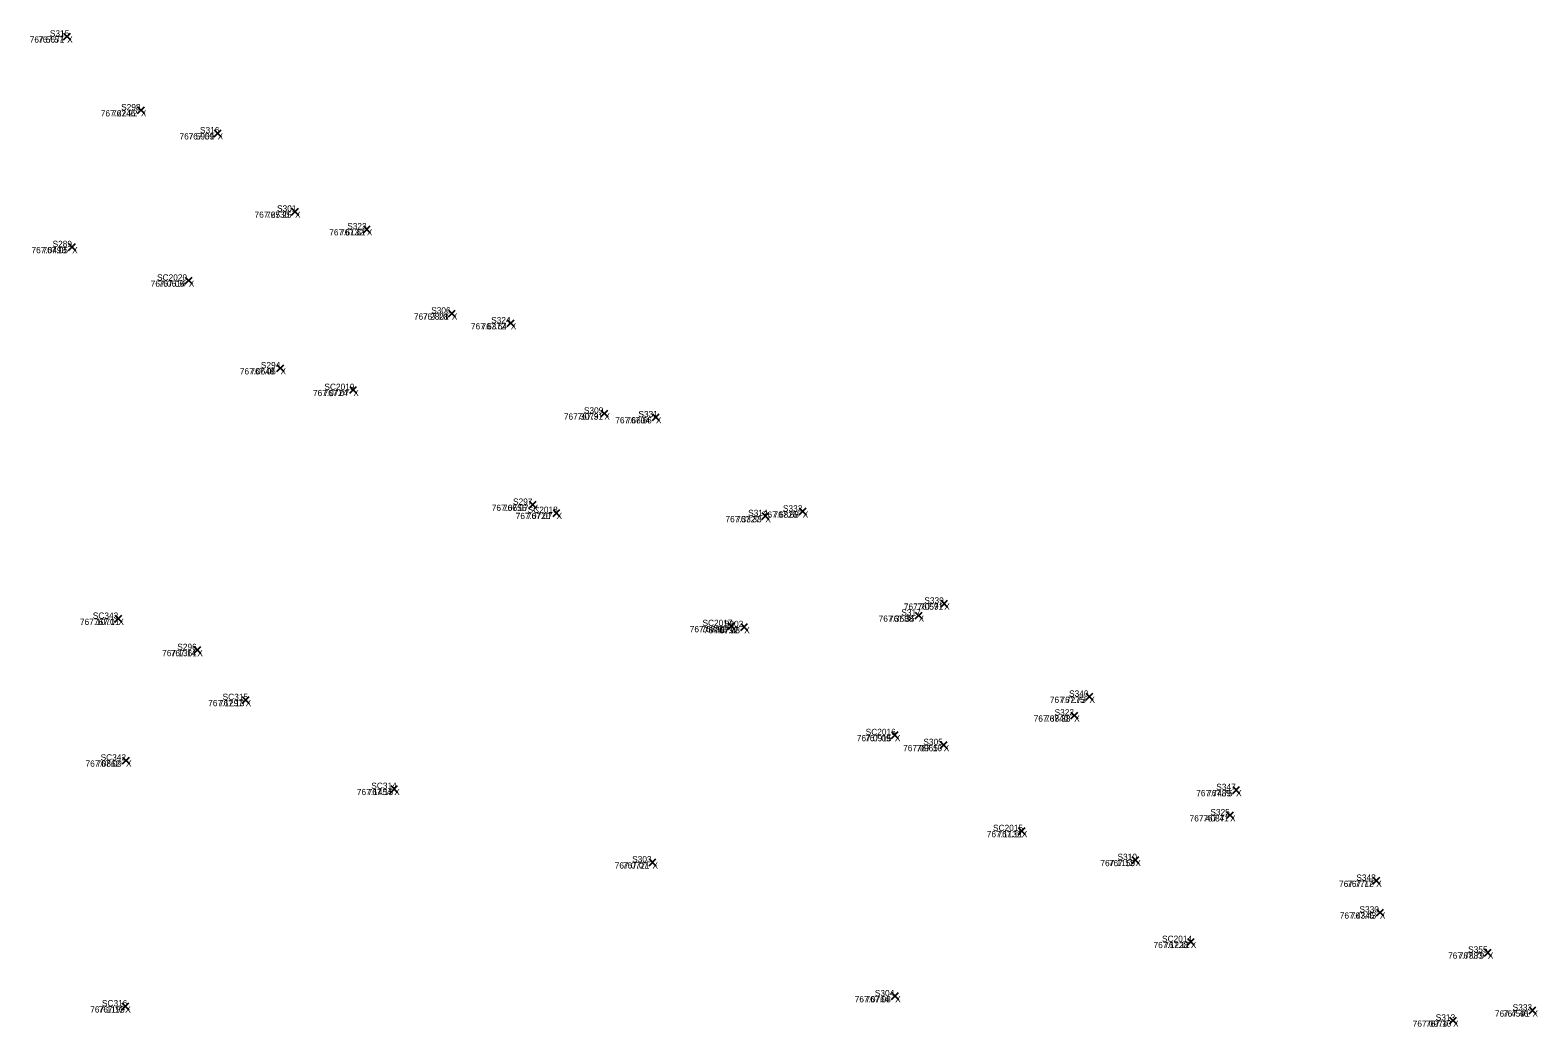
# Model space of a CAD drawing. Extents: x 1845019 to 1877956, y 680444 to 701081.
# Drawn here: x 1857662.66 to 1857677.19, y 694290.37 to 694299.98 of the extents above; entities that cross this region are included whole.
import ezdxf

# ---------------------------------------------------------------- set-up
doc = ezdxf.new("R2010")
doc.units = 0
for name, color, linetype in [('SV_X_Random_Point', 7, 'Continuous'), ('SV_X_Text_Comment', 7, 'Continuous'), ('SV_X_Text_Elevation', 7, 'Continuous'), ('SV_X_Text_Name', 7, 'Continuous')]:
    doc.layers.add(name, color=color, linetype=linetype)

msp = doc.modelspace()

# ---------------------------------------------------------------- linework, layer by layer
at = {"layer": 'SV_X_Random_Point'}
for p, q in [((1857662.984, 694299.886), (1857663.051, 694299.952)), ((1857662.984, 694299.952), (1857663.051, 694299.886)), ((1857662.984, 694299.886), (1857663.051, 694299.952)), ((1857662.984, 694299.952), (1857663.051, 694299.886)), ((1857663.695, 694299.175), (1857663.762, 694299.241)), ((1857663.695, 694299.241), (1857663.762, 694299.175)), ((1857663.695, 694299.175), (1857663.762, 694299.241)), ((1857663.695, 694299.241), (1857663.762, 694299.175)), ((1857664.435, 694298.953), (1857664.502, 694299.019)), ((1857664.435, 694299.019), (1857664.502, 694298.953)), ((1857664.435, 694298.953), (1857664.502, 694299.019)), ((1857664.435, 694299.019), (1857664.502, 694298.953)), ((1857665.18, 694298.197), (1857665.247, 694298.264)), ((1857665.18, 694298.264), (1857665.247, 694298.197)), ((1857665.18, 694298.197), (1857665.247, 694298.264)), ((1857665.18, 694298.264), (1857665.247, 694298.197)), ((1857665.873, 694298.027), (1857665.939, 694298.094)), ((1857665.873, 694298.094), (1857665.939, 694298.027)), ((1857665.873, 694298.027), (1857665.939, 694298.094)), ((1857665.873, 694298.094), (1857665.939, 694298.027)), ((1857663.032, 694297.856), (1857663.099, 694297.923)), ((1857663.032, 694297.923), (1857663.099, 694297.856)), ((1857663.032, 694297.856), (1857663.099, 694297.923)), ((1857663.032, 694297.923), (1857663.099, 694297.856)), ((1857664.156, 694297.533), (1857664.223, 694297.6)), ((1857664.156, 694297.6), (1857664.223, 694297.533)), ((1857664.156, 694297.533), (1857664.223, 694297.6)), ((1857664.156, 694297.6), (1857664.223, 694297.533)), ((1857666.692, 694297.215), (1857666.759, 694297.282)), ((1857666.692, 694297.282), (1857666.759, 694297.215)), ((1857666.692, 694297.215), (1857666.759, 694297.282)), ((1857666.692, 694297.282), (1857666.759, 694297.215)), ((1857667.26, 694297.122), (1857667.326, 694297.188)), ((1857667.26, 694297.188), (1857667.326, 694297.122)), ((1857667.26, 694297.122), (1857667.326, 694297.188)), ((1857667.26, 694297.188), (1857667.326, 694297.122)), ((1857665.04, 694296.688), (1857665.107, 694296.754)), ((1857665.04, 694296.754), (1857665.107, 694296.688)), ((1857665.04, 694296.688), (1857665.107, 694296.754)), ((1857665.04, 694296.754), (1857665.107, 694296.688)), ((1857665.741, 694296.479), (1857665.808, 694296.545)), ((1857665.741, 694296.545), (1857665.808, 694296.479)), ((1857665.741, 694296.479), (1857665.808, 694296.545)), ((1857665.741, 694296.545), (1857665.808, 694296.479)), ((1857668.162, 694296.252), (1857668.228, 694296.318)), ((1857668.162, 694296.318), (1857668.228, 694296.252)), ((1857668.162, 694296.252), (1857668.228, 694296.318)), ((1857668.162, 694296.318), (1857668.228, 694296.252)), ((1857668.659, 694296.216), (1857668.725, 694296.282)), ((1857668.659, 694296.282), (1857668.725, 694296.216)), ((1857668.659, 694296.216), (1857668.725, 694296.282)), ((1857668.659, 694296.282), (1857668.725, 694296.216)), ((1857667.471, 694295.372), (1857667.537, 694295.439)), ((1857667.471, 694295.439), (1857667.537, 694295.372)), ((1857667.471, 694295.372), (1857667.537, 694295.439)), ((1857667.471, 694295.439), (1857667.537, 694295.372)), ((1857667.701, 694295.293), (1857667.767, 694295.36)), ((1857667.701, 694295.36), (1857667.767, 694295.293)), ((1857667.701, 694295.293), (1857667.767, 694295.36)), ((1857667.701, 694295.36), (1857667.767, 694295.293)), ((1857670.074, 694295.307), (1857670.14, 694295.374)), ((1857670.074, 694295.374), (1857670.14, 694295.307)), ((1857670.074, 694295.307), (1857670.14, 694295.374)), ((1857670.074, 694295.374), (1857670.14, 694295.307)), ((1857669.714, 694295.263), (1857669.781, 694295.329)), ((1857669.714, 694295.329), (1857669.781, 694295.263)), ((1857669.714, 694295.263), (1857669.781, 694295.329)), ((1857669.714, 694295.329), (1857669.781, 694295.263)), ((1857671.437, 694294.419), (1857671.504, 694294.486)), ((1857671.437, 694294.486), (1857671.504, 694294.419)), ((1857671.437, 694294.419), (1857671.504, 694294.486)), ((1857671.437, 694294.486), (1857671.504, 694294.419)), ((1857663.478, 694294.273), (1857663.544, 694294.34)), ((1857663.478, 694294.34), (1857663.544, 694294.273)), ((1857663.478, 694294.273), (1857663.544, 694294.34)), ((1857663.478, 694294.34), (1857663.544, 694294.273)), ((1857671.191, 694294.304), (1857671.257, 694294.371)), ((1857671.191, 694294.371), (1857671.257, 694294.304)), ((1857671.191, 694294.304), (1857671.257, 694294.371)), ((1857671.191, 694294.371), (1857671.257, 694294.304)), ((1857669.385, 694294.203), (1857669.452, 694294.27)), ((1857669.385, 694294.27), (1857669.452, 694294.203)), ((1857669.385, 694294.203), (1857669.452, 694294.27)), ((1857669.385, 694294.27), (1857669.452, 694294.203)), ((1857669.51, 694294.193), (1857669.576, 694294.26)), ((1857669.51, 694294.26), (1857669.576, 694294.193)), ((1857669.51, 694294.193), (1857669.576, 694294.26)), ((1857669.51, 694294.26), (1857669.576, 694294.193)), ((1857664.239, 694293.971), (1857664.305, 694294.038)), ((1857664.239, 694294.038), (1857664.305, 694293.971)), ((1857664.239, 694293.971), (1857664.305, 694294.038)), ((1857664.239, 694294.038), (1857664.305, 694293.971)), ((1857672.837, 694293.522), (1857672.904, 694293.588)), ((1857672.837, 694293.588), (1857672.904, 694293.522)), ((1857672.837, 694293.522), (1857672.904, 694293.588)), ((1857672.837, 694293.588), (1857672.904, 694293.522)), ((1857664.705, 694293.49), (1857664.771, 694293.556)), ((1857664.705, 694293.556), (1857664.771, 694293.49)), ((1857664.705, 694293.49), (1857664.771, 694293.556)), ((1857664.705, 694293.556), (1857664.771, 694293.49)), ((1857672.69, 694293.34), (1857672.757, 694293.407)), ((1857672.69, 694293.407), (1857672.757, 694293.34)), ((1857672.69, 694293.34), (1857672.757, 694293.407)), ((1857672.69, 694293.407), (1857672.757, 694293.34)), ((1857670.962, 694293.151), (1857671.028, 694293.218)), ((1857670.962, 694293.218), (1857671.028, 694293.151)), ((1857670.962, 694293.151), (1857671.028, 694293.218)), ((1857670.962, 694293.218), (1857671.028, 694293.151)), ((1857671.433, 694293.056), (1857671.5, 694293.122)), ((1857671.433, 694293.122), (1857671.5, 694293.056)), ((1857671.433, 694293.056), (1857671.5, 694293.122)), ((1857671.433, 694293.122), (1857671.5, 694293.056)), ((1857663.552, 694292.906), (1857663.619, 694292.973)), ((1857663.552, 694292.973), (1857663.619, 694292.906)), ((1857663.552, 694292.906), (1857663.619, 694292.973)), ((1857663.552, 694292.973), (1857663.619, 694292.906)), ((1857666.137, 694292.632), (1857666.203, 694292.699)), ((1857666.137, 694292.699), (1857666.203, 694292.632)), ((1857666.137, 694292.632), (1857666.203, 694292.699)), ((1857666.137, 694292.699), (1857666.203, 694292.632)), ((1857674.251, 694292.622), (1857674.317, 694292.689)), ((1857674.251, 694292.689), (1857674.317, 694292.622)), ((1857674.251, 694292.622), (1857674.317, 694292.689)), ((1857674.251, 694292.689), (1857674.317, 694292.622)), ((1857674.193, 694292.379), (1857674.259, 694292.445)), ((1857674.193, 694292.445), (1857674.259, 694292.379)), ((1857674.193, 694292.379), (1857674.259, 694292.445)), ((1857674.193, 694292.445), (1857674.259, 694292.379)), ((1857672.185, 694292.227), (1857672.251, 694292.294)), ((1857672.185, 694292.294), (1857672.251, 694292.227)), ((1857672.185, 694292.227), (1857672.251, 694292.294)), ((1857672.185, 694292.294), (1857672.251, 694292.227)), ((1857668.626, 694291.925), (1857668.693, 694291.992)), ((1857668.626, 694291.992), (1857668.693, 694291.925)), ((1857668.626, 694291.925), (1857668.693, 694291.992)), ((1857668.626, 694291.992), (1857668.693, 694291.925)), ((1857673.28, 694291.948), (1857673.347, 694292.014)), ((1857673.28, 694292.014), (1857673.347, 694291.948)), ((1857673.28, 694291.948), (1857673.347, 694292.014)), ((1857673.28, 694292.014), (1857673.347, 694291.948)), ((1857675.601, 694291.747), (1857675.668, 694291.814)), ((1857675.601, 694291.814), (1857675.668, 694291.747)), ((1857675.601, 694291.747), (1857675.668, 694291.814)), ((1857675.601, 694291.814), (1857675.668, 694291.747)), ((1857675.636, 694291.441), (1857675.703, 694291.508)), ((1857675.636, 694291.508), (1857675.703, 694291.441)), ((1857675.636, 694291.441), (1857675.703, 694291.508)), ((1857675.636, 694291.508), (1857675.703, 694291.441)), ((1857673.814, 694291.158), (1857673.88, 694291.225)), ((1857673.814, 694291.225), (1857673.88, 694291.158)), ((1857673.814, 694291.158), (1857673.88, 694291.225)), ((1857673.814, 694291.225), (1857673.88, 694291.158)), ((1857676.677, 694291.055), (1857676.743, 694291.122)), ((1857676.677, 694291.122), (1857676.743, 694291.055)), ((1857676.677, 694291.055), (1857676.743, 694291.122)), ((1857676.677, 694291.122), (1857676.743, 694291.055)), ((1857670.964, 694290.635), (1857671.031, 694290.702)), ((1857670.964, 694290.702), (1857671.031, 694290.635)), ((1857670.964, 694290.635), (1857671.031, 694290.702)), ((1857670.964, 694290.702), (1857671.031, 694290.635)), ((1857663.545, 694290.536), (1857663.612, 694290.603)), ((1857663.545, 694290.603), (1857663.612, 694290.536)), ((1857663.545, 694290.536), (1857663.612, 694290.603)), ((1857663.545, 694290.603), (1857663.612, 694290.536)), ((1857677.107, 694290.497), (1857677.174, 694290.564)), ((1857677.107, 694290.564), (1857677.174, 694290.497)), ((1857677.107, 694290.497), (1857677.174, 694290.564)), ((1857677.107, 694290.564), (1857677.174, 694290.497)), ((1857676.342, 694290.4), (1857676.409, 694290.466)), ((1857676.342, 694290.466), (1857676.409, 694290.4)), ((1857676.342, 694290.4), (1857676.409, 694290.466)), ((1857676.342, 694290.466), (1857676.409, 694290.4))]:
    msp.add_line(p, q, dxfattribs=at)

# ---------------------------------------------------------------- texts
at = {"layer": 'SV_X_Text_Comment'}
for p in [(1857663.018, 694299.859), (1857663.728, 694299.148), (1857664.468, 694298.926), (1857665.214, 694298.171), (1857665.906, 694298.001), (1857663.066, 694297.829), (1857664.19, 694297.506), (1857666.725, 694297.189), (1857667.293, 694297.095), (1857665.074, 694296.661), (1857665.775, 694296.452), (1857668.195, 694296.225), (1857668.692, 694296.189), (1857667.504, 694295.345), (1857670.107, 694295.28), (1857667.734, 694295.267), (1857669.747, 694295.236), (1857671.224, 694294.277), (1857671.471, 694294.393), (1857663.511, 694294.246), (1857669.418, 694294.176), (1857669.543, 694294.166), (1857664.272, 694293.945), (1857664.738, 694293.463), (1857672.87, 694293.495), (1857672.723, 694293.314), (1857670.995, 694293.125), (1857671.466, 694293.029), (1857663.585, 694292.88), (1857666.17, 694292.606), (1857674.284, 694292.595), (1857674.226, 694292.352), (1857672.218, 694292.2), (1857668.659, 694291.898), (1857673.313, 694291.921), (1857675.634, 694291.721), (1857675.669, 694291.415), (1857673.847, 694291.131), (1857676.71, 694291.029), (1857663.578, 694290.51), (1857670.998, 694290.608), (1857676.375, 694290.373), (1857677.14, 694290.47)]:
    msp.add_text('X', height=0.06, dxfattribs=at).set_placement(p)
at = {"layer": 'SV_X_Text_Elevation'}
for s, p in [('767.5671', (1857662.657, 694299.859)), ('767.57', (1857662.738, 694299.859)), ('767.2246', (1857663.342, 694299.148)), ('767.22', (1857663.45, 694299.148)), ('767.5901', (1857664.101, 694298.926)), ('767.59', (1857664.188, 694298.926)), ('767.2530', (1857664.824, 694298.171)), ('767.25', (1857664.935, 694298.171)), ('767.6132', (1857665.544, 694298.001)), ('767.61', (1857665.648, 694298.001)), ('767.0498', (1857662.674, 694297.829)), ('767.05', (1857662.78, 694297.829)), ('767.0614', (1857663.823, 694297.506)), ('767.06', (1857663.9, 694297.506)), ('767.2801', (1857666.36, 694297.189)), ('767.28', (1857666.446, 694297.189)), ('767.6372', (1857666.909, 694297.095)), ('767.64', (1857667.012, 694297.095)), ('767.0648', (1857664.682, 694296.661)), ('767.06', (1857664.784, 694296.661)), ('767.0724', (1857665.387, 694296.452)), ('767.07', (1857665.489, 694296.452)), ('767.3079', (1857667.805, 694296.225)), ('767.31', (1857667.936, 694296.225)), ('767.6604', (1857668.301, 694296.189)), ('767.66', (1857668.407, 694296.189)), ('767.0656', (1857667.11, 694295.345)), ('767.07', (1857667.218, 694295.345)), ('767.6825', (1857669.723, 694295.28)), ('767.68', (1857669.825, 694295.28)), ('767.0720', (1857667.341, 694295.267)), ('767.07', (1857667.448, 694295.267)), ('767.3327', (1857669.362, 694295.236)), ('767.33', (1857669.466, 694295.236)), ('767.3588', (1857670.839, 694294.277)), ('767.36', (1857670.939, 694294.277)), ('767.7059', (1857671.082, 694294.393)), ('767.71', (1857671.214, 694294.393)), ('767.1070', (1857663.141, 694294.246)), ('767.11', (1857663.277, 694294.246)), ('767.0800', (1857669.018, 694294.176)), ('767.08', (1857669.132, 694294.176)), ('767.0792', (1857669.154, 694294.166)), ('767.08', (1857669.257, 694294.166)), ('767.1361', (1857663.933, 694293.945)), ('767.14', (1857664.016, 694293.945)), ('767.1297', (1857664.377, 694293.463)), ('767.13', (1857664.481, 694293.463)), ('767.7275', (1857672.489, 694293.495)), ('767.73', (1857672.591, 694293.495)), ('767.3840', (1857672.333, 694293.314)), ('767.38', (1857672.442, 694293.314)), ('767.0915', (1857670.628, 694293.125)), ('767.09', (1857670.709, 694293.125)), ('767.0965', (1857671.075, 694293.029)), ('767.10', (1857671.205, 694293.029)), ('767.0862', (1857663.195, 694292.88)), ('767.09', (1857663.299, 694292.88)), ('767.1454', (1857665.81, 694292.606)), ('767.15', (1857665.914, 694292.606)), ('767.7489', (1857673.9, 694292.595)), ('767.75', (1857674.005, 694292.595)), ('767.4087', (1857673.836, 694292.352)), ('767.41', (1857673.968, 694292.352)), ('767.1132', (1857671.881, 694292.2)), ('767.11', (1857671.984, 694292.2)), ('767.0721', (1857668.295, 694291.898)), ('767.07', (1857668.373, 694291.898)), ('767.1159', (1857672.976, 694291.921)), ('767.12', (1857673.057, 694291.921)), ('767.7712', (1857675.276, 694291.721)), ('767.77', (1857675.355, 694291.721)), ('767.4345', (1857675.283, 694291.415)), ('767.43', (1857675.389, 694291.415)), ('767.1228', (1857673.488, 694291.131)), ('767.12', (1857673.591, 694291.131)), ('767.7883', (1857676.327, 694291.029)), ('767.79', (1857676.43, 694291.029)), ('767.1199', (1857663.24, 694290.51)), ('767.12', (1857663.322, 694290.51)), ('767.0764', (1857670.608, 694290.608)), ('767.08', (1857670.711, 694290.608)), ('767.0974', (1857675.986, 694290.373)), ('767.10', (1857676.114, 694290.373)), ('767.4591', (1857676.778, 694290.47)), ('767.46', (1857676.856, 694290.47))]:
    msp.add_text(s, height=0.06, dxfattribs=at).set_placement(p)
at = {"layer": 'SV_X_Text_Name'}
for s, p in [('S315', (1857662.851, 694299.919)), ('S315', (1857662.851, 694299.919)), ('S298', (1857663.538, 694299.208)), ('S298', (1857663.538, 694299.208)), ('S316', (1857664.298, 694298.986)), ('S316', (1857664.298, 694298.986)), ('S301', (1857665.04, 694298.231)), ('S301', (1857665.041, 694298.231)), ('S323', (1857665.717, 694298.061)), ('S323', (1857665.717, 694298.061)), ('S289', (1857662.877, 694297.889)), ('S289', (1857662.877, 694297.889)), ('SC2020', (1857663.884, 694297.566)), ('SC2020', (1857663.884, 694297.566)), ('S306', (1857666.526, 694297.249)), ('S306', (1857666.526, 694297.249)), ('S324', (1857667.104, 694297.155)), ('S324', (1857667.104, 694297.155)), ('S294', (1857664.885, 694296.721)), ('S294', (1857664.885, 694296.721)), ('SC2019', (1857665.497, 694296.512)), ('SC2019', (1857665.497, 694296.512)), ('S309', (1857667.998, 694296.285)), ('S309', (1857667.998, 694296.285)), ('S331', (1857668.523, 694296.249)), ('S331', (1857668.524, 694296.249)), ('S297', (1857667.315, 694295.405)), ('S297', (1857667.315, 694295.405)), ('SC2018', (1857667.456, 694295.327)), ('SC2018', (1857667.456, 694295.327)), ('S314', (1857669.581, 694295.296)), ('S314', (1857669.581, 694295.296)), ('S332', (1857669.916, 694295.34)), ('S332', (1857669.916, 694295.34)), ('S339', (1857671.279, 694294.453)), ('S339', (1857671.279, 694294.453)), ('SC343', (1857663.265, 694294.306)), ('SC343', (1857663.265, 694294.306)), ('S317', (1857671.057, 694294.337)), ('S317', (1857671.057, 694294.337)), ('SC2017', (1857669.141, 694294.236)), ('SC2017', (1857669.141, 694294.236)), ('S302', (1857669.347, 694294.226)), ('S302', (1857669.347, 694294.226)), ('S296', (1857664.079, 694294.005)), ('S296', (1857664.079, 694294.005)), ('S340', (1857672.674, 694293.555)), ('S340', (1857672.674, 694293.555)), ('SC315', (1857664.516, 694293.523)), ('SC315', (1857664.516, 694293.523)), ('S322', (1857672.534, 694293.374)), ('S322', (1857672.534, 694293.374)), ('SC2016', (1857670.714, 694293.185)), ('SC2016', (1857670.714, 694293.185)), ('S305', (1857671.27, 694293.089)), ('S305', (1857671.27, 694293.089)), ('SC342', (1857663.34, 694292.94)), ('SC342', (1857663.34, 694292.94)), ('SC314', (1857665.949, 694292.666)), ('SC314', (1857665.949, 694292.666)), ('S347', (1857674.093, 694292.655)), ('S347', (1857674.093, 694292.655)), ('S325', (1857674.036, 694292.412)), ('S325', (1857674.036, 694292.412)), ('SC2015', (1857671.941, 694292.26)), ('SC2015', (1857671.941, 694292.26)), ('S303', (1857668.463, 694291.958)), ('S303', (1857668.463, 694291.958)), ('S310', (1857673.141, 694291.981)), ('S310', (1857673.141, 694291.981)), ('S348', (1857675.443, 694291.781)), ('S348', (1857675.443, 694291.781)), ('S330', (1857675.473, 694291.475)), ('S330', (1857675.473, 694291.475)), ('SC2014', (1857673.57, 694291.191)), ('SC2014', (1857673.57, 694291.191)), ('S355', (1857676.52, 694291.089)), ('S355', (1857676.52, 694291.089)), ('S304', (1857670.802, 694290.668)), ('S304', (1857670.802, 694290.668)), ('SC316', (1857663.353, 694290.57)), ('SC316', (1857663.353, 694290.57)), ('S333', (1857676.949, 694290.53)), ('S333', (1857676.949, 694290.53)), ('S313', (1857676.208, 694290.433)), ('S313', (1857676.208, 694290.433))]:
    msp.add_text(s, height=0.06, dxfattribs=at).set_placement(p)

doc.saveas('drawing.dxf')
